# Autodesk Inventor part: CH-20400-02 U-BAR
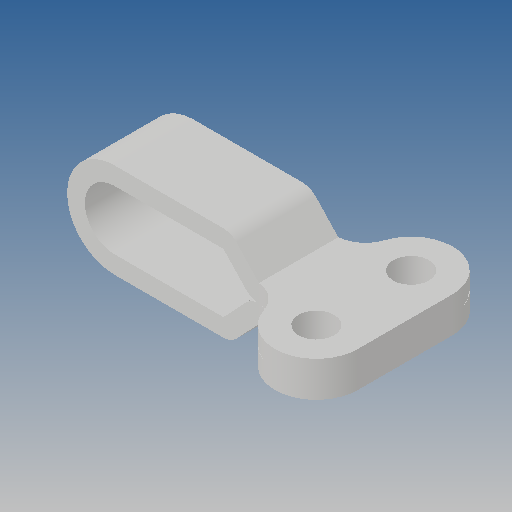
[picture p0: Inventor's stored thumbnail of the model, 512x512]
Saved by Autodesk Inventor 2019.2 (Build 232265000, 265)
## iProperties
Created: 2012-09
Part Number: CH-20400-02 U-BAR
Material: Ogólny
Document SubType Name: Modeling
Designer: CADENGINEERING4
Density: 1 g/cm^3
Appearance: Domyślna
Author: CADENGINEERING4
Revision Number: ÈÎºÎ
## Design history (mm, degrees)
feature "ÇÐ³ý-À­Éì3"
feature "¾µÏò1"
node "Bryła1"
node "Bryła2"
